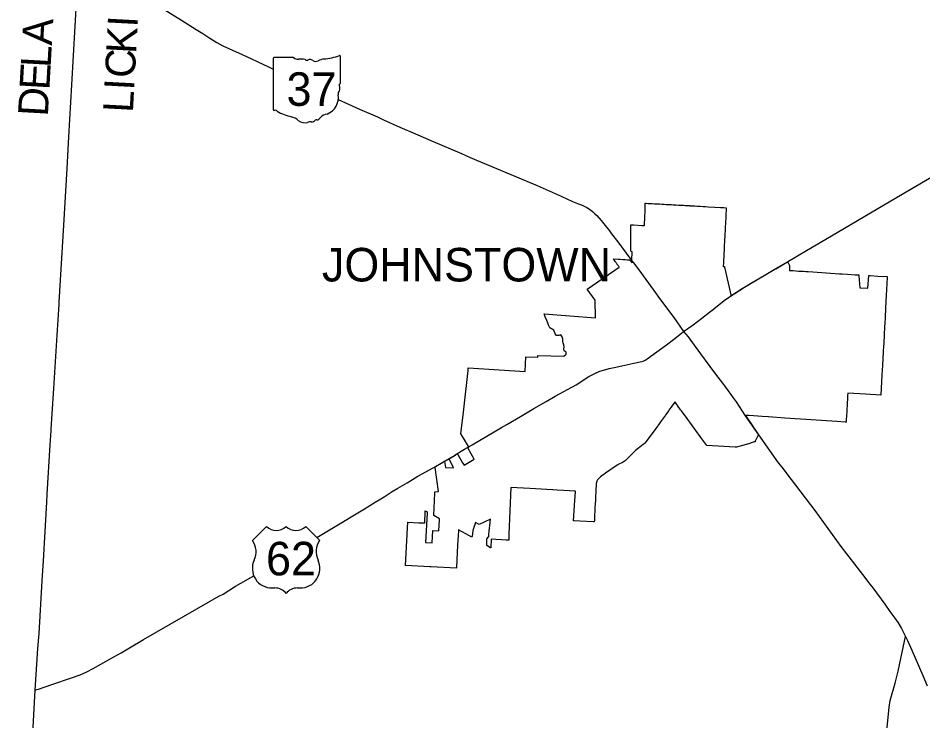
# Model space of a CAD drawing. Extents: x 1853412 to 2125412, y 78841 to 855418.
# Drawn here: x 1894590 to 1924799, y 771538 to 795017 of the extents above; entities that cross this region are included whole.
import ezdxf

# ---------------------------------------------------------------- set-up
doc = ezdxf.new("R2010")
doc.units = 0
for name, color, linetype in [('GM_X_Corporation', 7, 'Continuous'), ('GM_X_Corporation_Text', 7, 'Continuous'), ('GM_X_County', 7, 'Continuous'), ('GM_X_County_Text', 7, 'Continuous'), ('GM_X_State_Location', 7, 'Continuous'), ('GM_X_State_Route', 7, 'Continuous'), ('GM_X_State_Shield', 7, 'Continuous'), ('GM_X_US_Location', 7, 'Continuous'), ('GM_X_US_Route', 7, 'Continuous'), ('GM_X_US_Shield', 7, 'Continuous'), ('UT_P_Electric', 7, 'Continuous')]:
    doc.layers.add(name, color=color, linetype=linetype)

msp = doc.modelspace()

# ---------------------------------------------------------------- linework, layer by layer
at = {"layer": 'GM_X_Corporation'}
msp.add_lwpolyline([(1914197, 779811), (1914145, 779773), (1914124, 779756), (1914035, 779689), (1914001, 779659), (1913990, 779649), (1913979, 779639), (1913974, 779634), (1913968, 779628), (1913952, 779614), (1913938, 779594), (1913925, 779574), (1913909, 779544), (1913902, 779519), (1913896, 779494), (1913892, 779475), (1913888, 779406), (1913887, 779394), (1913882, 779286), (1913880, 779222), (1913879, 779198), (1913870, 779036), (1913868, 778999), (1913867, 778992), (1913867, 778986), (1913863, 778912), (1913855, 778787), (1913850, 778658), (1913844, 778537), (1913838, 778423), (1913837, 778405), (1913831, 778287), (1913831, 778275), (1913830, 778262), (1913829, 778235), (1913827, 778192), (1913826, 778189), (1913796, 778191), (1913342, 778208), (1913160, 778217), (1913136, 778218), (1913167, 778737), (1913200, 779213), (1912795, 779234), (1912587, 779246), (1912441, 779255), (1912428, 779255), (1911676, 779299), (1911043, 779336), (1910979, 777775), (1910970, 777571), (1910880, 777576), (1910727, 777585), (1910545, 777596), (1910382, 777605), (1910374, 777344), (1910372, 777320), (1910366, 777323), (1910236, 777393), (1910237, 777430), (1910241, 777620), (1910304, 777696), (1910306, 777713), (1910312, 777780), (1910319, 777862), (1910320, 777873), (1910346, 778162), (1910347, 778174), (1910357, 778282), (1909986, 778099), (1909860, 778171), (1909777, 777902), (1909747, 777703), (1909742, 777672), (1909538, 777788), (1909292, 777925), (1909290, 777892), (1909281, 777727), (1909263, 777409), (1909224, 776659), (1909223, 776642), (1908374, 776687), (1908342, 776689), (1907526, 776732), (1907583, 777762), (1907585, 777789), (1907603, 778183), (1907965, 778159), (1908165, 778151), (1908183, 778521), (1908184, 778556), (1908246, 778521), (1908244, 778487), (1908244, 778474), (1908193, 777497), (1908418, 777487), (1908439, 777897), (1908638, 777887), (1908659, 778251), (1908661, 778285), (1908466, 778397), (1908468, 778415), (1908506, 779143), (1908508, 779186), (1908626, 779207), (1908515, 779999), (1908510, 780028), (1908827, 780208), (1908864, 780008), (1909127, 779988), (1908994, 780274), (1908982, 780300), (1909260, 780459), (1909275, 780433), (1909429, 780165), (1909436, 780153), (1909478, 780080), (1909822, 780287), (1909619, 780637), (1909604, 780663), (1909639, 780685), (1909624, 780709), (1909479, 780950), (1909370, 781133), (1909456, 781847), (1909616, 783242), (1909622, 783329), (1911522, 783214), (1911543, 783696), (1911947, 783692), (1911948, 783742), (1912815, 783721), (1912893, 783785), (1912891, 783853), (1912826, 783905), (1912808, 783972), (1912826, 784023), (1912816, 784101), (1912787, 784168), (1912779, 784210), (1912773, 784298), (1912760, 784374), (1912712, 784432), (1912648, 784412), (1912570, 784408), (1912517, 784466), (1912475, 784591), (1912348, 784673), (1912308, 784739), (1912265, 784857), (1912239, 784909), (1912190, 785042), (1912159, 785135), (1913870, 785009), (1913857, 785594), (1913593, 785961), (1914663, 786695), (1914654, 786708), (1914639, 786728), (1914625, 786748), (1914611, 786768), (1914596, 786789), (1914592, 786794), (1914581, 786809), (1914567, 786829), (1914552, 786850), (1914538, 786870), (1914523, 786890), (1914466, 786973), (1914475, 786972), (1914627, 786962), (1914692, 786958), (1914778, 786952), (1914781, 786952), (1914816, 786950), (1914854, 786947), (1914934, 786943), (1914974, 786941), (1915019, 786939), (1915028, 786919), (1915043, 786899), (1915057, 786878), (1915072, 786858), (1915087, 786838), (1915085, 786904), (1915085, 786925), (1915085, 786934), (1915087, 787206), (1915050, 787228), (1915048, 788111), (1915093, 788113), (1915124, 788111), (1915134, 788110), (1915412, 788093), (1915444, 788091), (1915505, 788088), (1915515, 788388), (1915521, 788566), (1915531, 788834), (1915562, 788832), (1915620, 788828), (1915756, 788821), (1915836, 788816), (1915853, 788815), (1915916, 788812), (1916002, 788807), (1916084, 788802), (1916164, 788798), (1916232, 788794), (1916244, 788794), (1916324, 788789), (1916404, 788785), (1916462, 788781), (1916484, 788780), (1916563, 788776), (1916643, 788771), (1916713, 788767), (1916723, 788767), (1916803, 788762), (1916861, 788759), (1916971, 788753), (1916992, 788752), (1917005, 788751), (1917018, 788750), (1917032, 788750), (1917105, 788746), (1917188, 788741), (1917276, 788736), (1917367, 788731), (1917467, 788725), (1917539, 788721), (1917630, 788716), (1917853, 788704), (1918046, 788693), (1918147, 788688), (1918234, 788682), (1918228, 788562), (1918224, 788501), (1918221, 788440), (1918220, 788414), (1918215, 788315), (1918210, 788223), (1918206, 788139), (1918201, 788057), (1918197, 787978), (1918193, 787898), (1918189, 787809), (1918184, 787716), (1918179, 787624), (1918174, 787530), (1918169, 787440), (1918166, 787374), (1918165, 787352), (1918160, 787262), (1918155, 787168), (1918154, 787146), (1918150, 787074), (1918142, 786911), (1918139, 786851), (1918132, 786722), (1918176, 786719), (1918180, 786698), (1918329, 786013), (1918381, 785772), (1918385, 785759), (1918387, 785739), (1918768, 785986), (1919500, 786417), (1919888, 786648), (1920278, 786878), (1920299, 786846), (1920348, 786756), (1920346, 786617), (1920345, 786588), (1920410, 786584), (1920465, 786580), (1920559, 786574), (1920646, 786568), (1920725, 786563), (1920787, 786559), (1920810, 786558), (1920890, 786552), (1920971, 786547), (1921120, 786537), (1921270, 786527), (1921420, 786517), (1921570, 786508), (1921719, 786498), (1921869, 786488), (1922019, 786478), (1922104, 786472), (1922277, 786461), (1922534, 786444), (1922576, 786441), (1922618, 786439), (1922663, 786436), (1922665, 786406), (1922691, 786009), (1922959, 785993), (1922991, 786416), (1922999, 786416), (1923042, 786413), (1923293, 786398), (1923611, 786383), (1923610, 786354), (1923576, 785748), (1923565, 785560), (1923535, 785038), (1923523, 784787), (1923520, 784733), (1923500, 784402), (1923478, 783995), (1923475, 783944), (1923471, 783863), (1923446, 783411), (1923429, 783103), (1923391, 782419), (1923391, 782419), (1922886, 782449), (1922289, 782484), (1922284, 782401), (1922281, 782331), (1922277, 782261), (1922274, 782191), (1922271, 782122), (1922267, 782052), (1922264, 781982), (1922262, 781954), (1922260, 781911), (1922257, 781841), (1922253, 781771), (1922242, 781554), (1922242, 781548), (1922241, 781519), (1922209, 781520), (1921927, 781540), (1921411, 781574), (1920193, 781655), (1919647, 781692), (1919630, 781693), (1919431, 781707), (1918994, 781740), (1918875, 781740), (1918898, 781706), (1919131, 781362), (1919144, 781343), (1919289, 781129), (1919307, 781102), (1919246, 780973), (1919237, 780953), (1919202, 780881), (1919195, 780866), (1919168, 780857), (1919141, 780848), (1919102, 780835), (1919069, 780825), (1919021, 780811), (1918570, 780679), (1918532, 780681), (1917582, 780739), (1917420, 780961), (1917162, 781315), (1916838, 781758), (1916836, 781761), (1916828, 781771), (1916739, 781892), (1916721, 781917), (1916710, 781933), (1916666, 781993), (1916622, 782053), (1916612, 782066), (1916579, 782111), (1916526, 782184), (1916522, 782190), (1916472, 782127), (1916415, 782049), (1916396, 782023), (1916387, 782009), (1916318, 781915), (1916306, 781897), (1916261, 781835), (1916219, 781774), (1916207, 781756), (1916175, 781713), (1916076, 781578), (1915910, 781346), (1915846, 781259), (1915694, 781051), (1915553, 780864), (1915538, 780847), (1915516, 780822), (1915494, 780797), (1915464, 780767), (1915207, 780573), (1915191, 780560), (1915035, 780406), (1914909, 780282), (1914858, 780232), (1914825, 780209), (1914807, 780197), (1914770, 780176), (1914628, 780103), (1914608, 780092), (1914529, 780042), (1914519, 780036)], close=True, dxfattribs=at)
at = {"layer": 'GM_X_County'}
msp.add_lwpolyline([(1894709, 764094), (1895160, 772568), (1895250, 773961), (1895288, 774454), (1895395, 776222), (1895436, 776881), (1895548, 778843), (1895564, 779108), (1895661, 780756), (1895691, 781228), (1895694, 781280), (1895726, 781801), (1895780, 782641), (1895890, 784424), (1895957, 785446), (1895960, 785523), (1896120, 788101), (1896225, 789997), (1896286, 791049), (1896383, 792786), (1896549, 795741)], dxfattribs=at)
at = {"layer": 'GM_X_State_Route'}
for points in [[(1923875, 772799), (1923970, 773202), (1924179, 774202), (1924222, 774362)], [(1923513, 769949), (1923599, 771204), (1923677, 772002), (1923708, 772217), (1923875, 772799)]]:
    msp.add_lwpolyline(points, dxfattribs=at)
at = {"layer": 'GM_X_State_Shield'}
for p, q in [((1903111, 793666), (1903111, 791965)), ((1903789, 793695), (1903133, 793695)), ((1905352, 792848), (1905352, 793738)), ((1905352, 792848), (1905352, 792848))]:
    msp.add_line(p, q, dxfattribs=at)
for centre, radius, start, end in [((1903137, 793670), 26, 98.1301, 188.1301), ((1903946, 793893), 252, 231.6195, 271.1119), ((1904029, 792740), 904, 80.4867, 94.9883), ((1904235, 793679), 72.7, 219.7921, 297.1024), ((1904341, 793482), 151, 54.4667, 119.1411), ((1904536, 793752), 182, 233.8562, 294.8282), ((1904857, 793176), 478, 97.3462, 120.7689), ((1904554, 796015), 2377, 275.8445, 288.9065), ((1905328, 793741), 25, 351.8621, 97.738), ((1905347, 792782), 38.6, 107.944, 210.337), ((1905101, 792670), 232, 340.033, 23.6496), ((1905326, 792844), 26.7, 289.6038, 7.7341), ((1904687, 792362), 595, 292.3089, 8.9858), ((1905442, 792475), 169, 136.8065, 186.9296), ((1903137, 791961), 26.2, 171.9584, 258.3066), ((1903141, 792135), 200, 267.339, 280.6039), ((1903182, 791867), 72.1, 29.7484, 93.2717), ((1904092, 793395), 1716, 240.4129, 257.1985), ((1904938, 791487), 326, 94.4031, 142.5768), ((1903580, 791201), 537, 47.1842, 75.836), ((1904161, 791858), 341, 230.7004, 286.2918), ((1904358, 791270), 280, 85.6951, 111.2099), ((1904383, 791731), 182, 268.777, 315.5493), ((1904547, 791566), 51.1, 65.7517, 132.6484), ((1904525, 791800), 192, 282.8732, 323.2771)]:
    msp.add_arc(centre, radius, start, end, dxfattribs=at)
at = {"layer": 'GM_X_US_Route'}
for p, q in [((1920317, 786898), (1920918, 787258)), ((1919519, 786425), (1919889, 786645)), ((1918782, 785991), (1919104, 786181)), ((1917125, 784773), (1917419, 784997)), ((1916811, 784546), (1917125, 784773))]:
    msp.add_line(p, q, dxfattribs=at)
for points in [[(1920918, 787258), (1921747, 787747), (1923730, 788911), (1924239, 789210), (1925529, 789975), (1926084, 790306), (1926387, 790487), (1928139, 791480), (1928618, 791769), (1928834, 791898), (1929033, 791991), (1929238, 792099), (1929476, 792233), (1929556, 792284), (1929873, 792462), (1931133, 793199), (1932237, 793864), (1933131, 794391), (1933547, 794637), (1934099, 794969), (1934865, 795428)], [(1919889, 786645), (1920279, 786875), (1920317, 786898)], [(1919104, 786181), (1919501, 786414), (1919519, 786425)], [(1918375, 785728), (1918777, 785989), (1918782, 785991)], [(1917823, 785307), (1918104, 785539), (1918206, 785618), (1918330, 785699)], [(1918330, 785699), (1918344, 785707), (1918375, 785728)], [(1917419, 784997), (1917671, 785190), (1917802, 785290), (1917823, 785307)]]:
    msp.add_lwpolyline(points, dxfattribs=at)
at = {"layer": 'GM_X_US_Shield'}
for p, q in [((1902884, 778034), (1902417, 777567)), ((1904659, 777567), (1904192, 778034)), ((1903071, 775979), (1903164, 775979)), ((1903912, 775979), (1904005, 775979))]:
    msp.add_line(p, q, dxfattribs=at)
for centre, radius, start, end in [((1903211, 778368), 467, 225.573, 314.427), ((1903865, 778368), 467, 225.573, 314.427), ((1901882, 777192), 654, 334.5471, 35.0009), ((1905194, 777192), 654, 144.9991, 205.4529), ((1903064, 776633), 654, 154.8319, 270.6383), ((1904012, 776633), 654, 269.3617, 25.1681), ((1903164, 775513), 467, 36.8699, 90), ((1903912, 775513), 467, 90, 143.1301)]:
    msp.add_arc(centre, radius, start, end, dxfattribs=at)
at = {"layer": 'UT_P_Electric'}
for p, q in [((1916513, 784317), (1916811, 784546)), ((1916467, 784282), (1916513, 784317)), ((1914692, 783385), (1914742, 783396)), ((1908771, 780182), (1908909, 780261)), ((1907081, 779202), (1907263, 779309))]:
    msp.add_line(p, q, dxfattribs=at)
for points in [[(1896641, 797536), (1897200, 796952), (1897643, 796497), (1897757, 796410), (1897911, 796297), (1898148, 796145), (1898807, 795733), (1899294, 795420), (1900041, 794949), (1900533, 794641), (1900757, 794500), (1900989, 794344), (1901226, 794196), (1901430, 794089), (1902072, 793798), (1902386, 793656), (1902948, 793385), (1903111, 793308)], [(1905278, 792299), (1905987, 791970), (1906589, 791714), (1906785, 791622), (1907336, 791370), (1907856, 791147), (1908448, 790897), (1909389, 790488), (1909682, 790360), (1910030, 790217), (1910432, 790046), (1911923, 789421), (1912725, 789067), (1913105, 788888), (1913266, 788826)], [(1913266, 788826), (1913427, 788764), (1913582, 788687), (1913700, 788606), (1913769, 788555), (1913850, 788483), (1913911, 788423), (1914059, 788252), (1914149, 788148), (1914334, 787909), (1914407, 787810), (1914615, 787545), (1915018, 786996)], [(1915018, 786996), (1915080, 786911), (1915142, 786842), (1915312, 786604), (1915779, 785964)], [(1915779, 785964), (1915813, 785919), (1916008, 785653), (1916478, 785010), (1916811, 784546)], [(1916811, 784546), (1916957, 784367), (1917162, 784087)], [(1915414, 783547), (1915462, 783558), (1915524, 783588), (1915593, 783631), (1916237, 784107), (1916467, 784282)], [(1917162, 784087), (1917499, 783634), (1917530, 783592)], [(1911810, 781973), (1912220, 782211), (1912522, 782385), (1913218, 782770), (1913646, 783040), (1913845, 783143), (1914018, 783220), (1914132, 783259), (1914321, 783307), (1914436, 783335)], [(1914436, 783335), (1914547, 783361), (1914692, 783385)], [(1914742, 783396), (1915145, 783486), (1915414, 783547)], [(1917530, 783592), (1917839, 783171), (1918142, 782775)], [(1918142, 782775), (1918172, 782736), (1918496, 782285)], [(1918496, 782285), (1918561, 782195), (1918869, 781731)], [(1910903, 781444), (1911359, 781713), (1911810, 781973)], [(1918869, 781731), (1919257, 781176), (1919311, 781097)], [(1909495, 780612), (1909748, 780765), (1910734, 781345), (1910903, 781444)], [(1919311, 781097), (1919969, 780165), (1920084, 780020), (1920403, 779603), (1921187, 778566), (1922063, 777370), (1922783, 776424), (1922990, 776153), (1923023, 776112)], [(1909178, 780421), (1909187, 780426), (1909495, 780612)], [(1908909, 780261), (1908914, 780263), (1909178, 780421)], [(1907763, 779604), (1907939, 779710), (1908448, 779998)], [(1908448, 779998), (1908467, 780008), (1908771, 780182)], [(1907263, 779309), (1907579, 779492), (1907763, 779604)], [(1906512, 778842), (1906643, 778923), (1906808, 779026), (1907081, 779202)], [(1906206, 778654), (1906250, 778680), (1906512, 778842)], [(1904563, 777663), (1905012, 777933), (1906206, 778654)], [(1898781, 774255), (1901002, 775535), (1901290, 775706), (1901434, 775777), (1901851, 776038), (1902457, 776390)], [(1923023, 776112), (1923129, 775979), (1923526, 775443), (1923699, 775198), (1923732, 775152)], [(1923732, 775152), (1923863, 774969), (1923971, 774820), (1924089, 774620), (1924222, 774362), (1924288, 774227), (1924426, 773903), (1924800, 773059), (1924937, 772708)], [(1895161, 772565), (1895215, 772584), (1895269, 772603), (1895716, 772755), (1896370, 772981), (1896665, 773083), (1896889, 773183), (1897092, 773286), (1897791, 773678), (1898036, 773816), (1898307, 773975), (1898781, 774255)]]:
    msp.add_lwpolyline(points, dxfattribs=at)

# ---------------------------------------------------------------- texts
at = {"layer": 'GM_X_Corporation_Text'}
msp.add_text('JOHNSTOWN', height=1120, rotation=0, dxfattribs=at).set_placement((1904735, 786219))
at = {"layer": 'GM_X_County_Text'}
for s, rotation, p in [('A', 86.784, (1895716, 794093)), ('I', 86.9312, (1898575, 794695)), ('K', 86.9325, (1898528, 793812)), ('L', 86.7841, (1895674, 793346)), ('C', 86.9328, (1898484, 792999)), ('E', 86.7841, (1895632, 792599)), ('I', 86.9328, (1898462, 792590)), ('D', 86.784, (1895582, 791716)), ('L', 86.9328, (1898422, 791843))]:
    msp.add_text(s, height=1000, rotation=rotation, dxfattribs=at).set_placement(p)
at = {"layer": 'GM_X_State_Location'}
for s, p in [('s', (1904181, 792693)), ('r', (1904181, 792693)), ('s', (1922388, 777002)), ('r', (1922388, 777002))]:
    msp.add_text(s, height=1, dxfattribs=at).set_placement(p)
for p in [(1903929, 792620), (1922136, 776930)]:
    msp.add_text('37', height=1, rotation=0, dxfattribs=at).set_placement(p)
at = {"layer": 'GM_X_State_Shield'}
msp.add_text('37', height=1120.7, dxfattribs=at).set_placement((1903553, 792085))
at = {"layer": 'GM_X_US_Location'}
msp.add_text('62', height=1, rotation=0, dxfattribs=at).set_placement((1903335, 776701))
for s in ['0', '/']:
    msp.add_text(s, height=1, dxfattribs=at).set_placement((1903541, 776908))
at = {"layer": 'GM_X_US_Shield'}
msp.add_text('62', height=1120.7, dxfattribs=at).set_placement((1902868, 776400))

doc.saveas('drawing.dxf')
